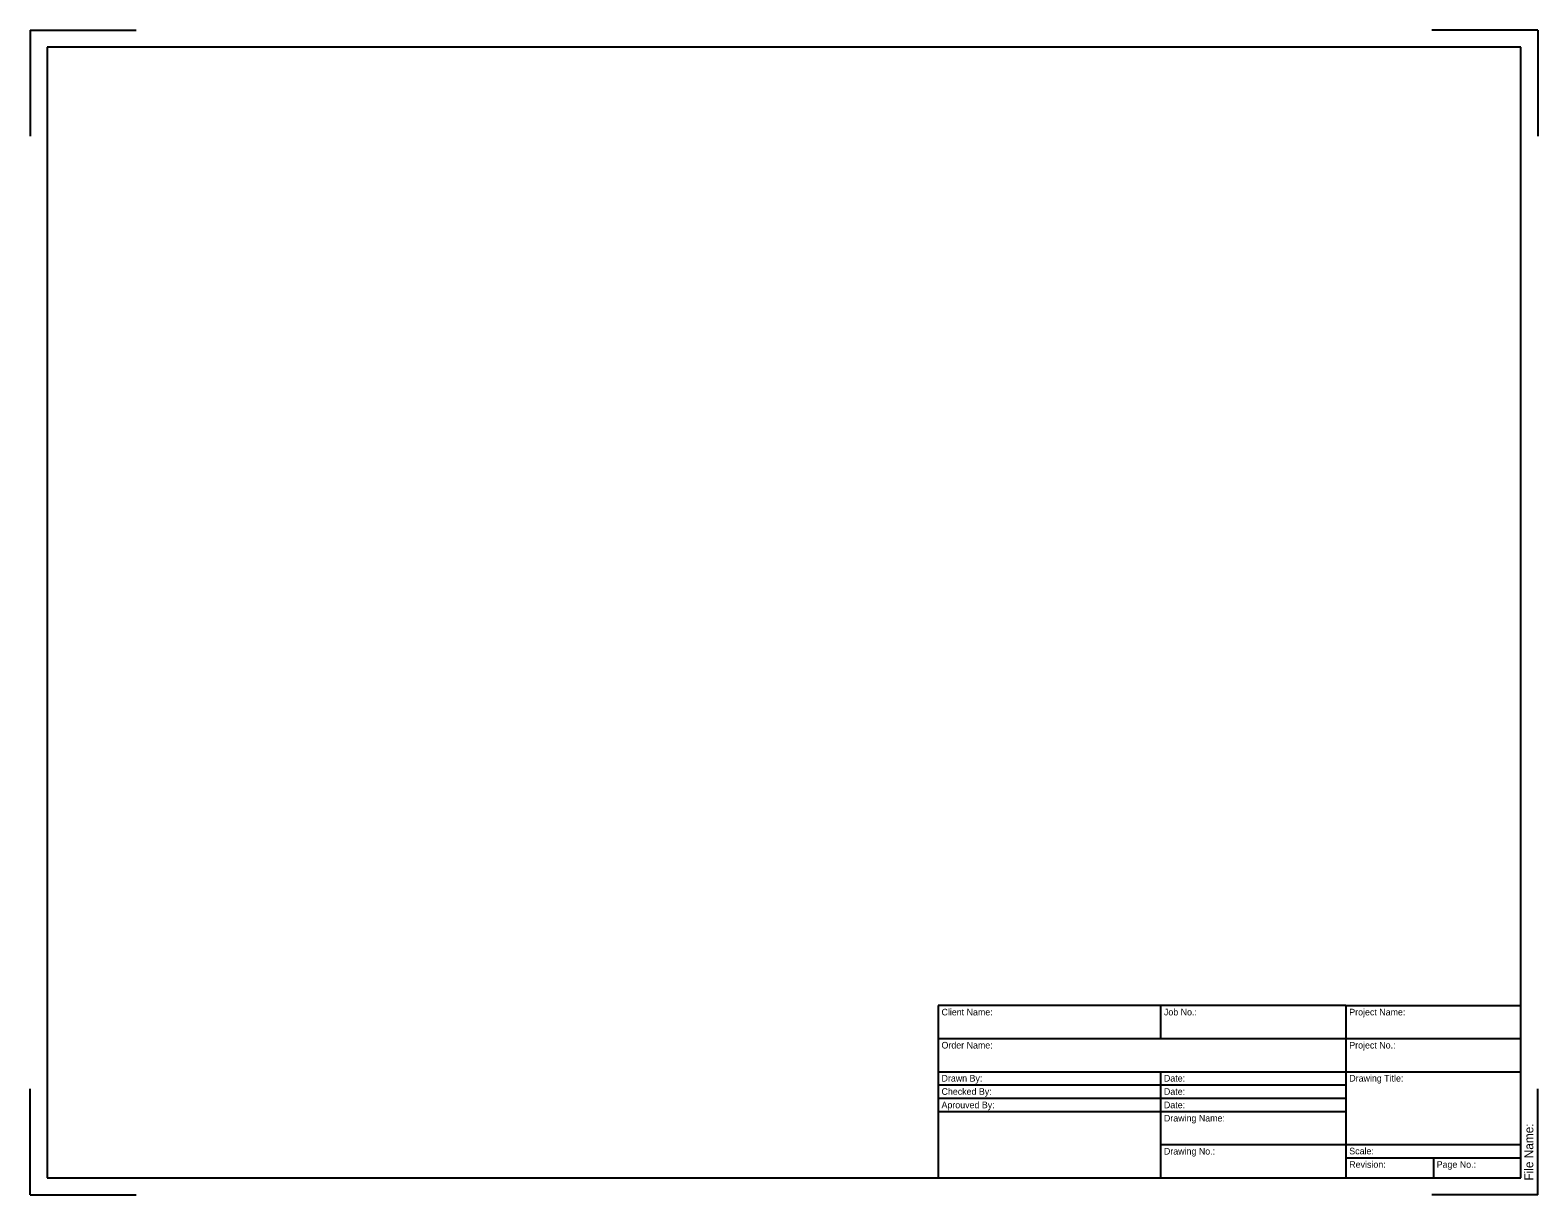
# Model space of a CAD drawing. Extents: x 0 to 44, y 0 to 34.
import ezdxf

# ---------------------------------------------------------------- set-up
doc = ezdxf.new("R2010")
doc.units = 0
doc.layers.add('STSF-BORDER', color=7, linetype='Continuous')

msp = doc.modelspace()

# ---------------------------------------------------------------- linework, layer by layer
at = {"layer": 'STSF-BORDER'}
for p, q in [((0, 34), (0, 30.909)), ((0, 34), (3.091, 34)), ((44, 34), (40.909, 34)), ((44, 34), (44, 30.909)), ((0.5, 33.5), (0.5, 0.5)), ((43.5, 33.5), (0.5, 33.5)), ((43.5, 0.5), (43.5, 33.5)), ((26.5, 5.528), (26.5, 0.5)), ((38.4, 5.528), (26.5, 5.528)), ((32.991, 5.528), (32.991, 4.562)), ((38.4, 5.528), (43.5, 5.528)), ((38.4, 5.528), (38.4, 0.5)), ((26.5, 4.562), (38.4, 4.562)), ((38.4, 4.562), (43.5, 4.562)), ((26.5, 3.596), (38.4, 3.596)), ((32.991, 3.596), (32.991, 0.5)), ((38.4, 3.596), (43.5, 3.596)), ((0, 0), (0, 3.091)), ((26.5, 3.21), (32.991, 3.21)), ((32.991, 3.21), (38.4, 3.21)), ((44, 0), (44, 3.091)), ((26.5, 2.824), (32.991, 2.824)), ((32.991, 2.824), (38.4, 2.824)), ((26.5, 2.432), (32.991, 2.432)), ((32.991, 2.432), (38.4, 2.432)), ((32.991, 1.466), (38.4, 1.466)), ((38.4, 1.471), (43.5, 1.471)), ((38.4, 1.085), (43.5, 1.085)), ((40.95, 1.085), (40.95, 0.5)), ((0.5, 0.5), (43.5, 0.5)), ((32.991, 0.5), (38.4, 0.5)), ((0, 0), (3.091, 0)), ((44, 0), (40.909, 0))]:
    msp.add_line(p, q, dxfattribs=at)

# ---------------------------------------------------------------- texts
for s, height, p in [('Client Name:', 0.19318, (26.597, 5.238)), ('Job No.:', 0.1932, (33.088, 5.238)), ('Project Name:', 0.19318, (38.497, 5.238)), ('Order Name:', 0.19318, (26.597, 4.272)), ('Project No.:', 0.19318, (38.497, 4.272)), ('Checked By:', 0.19318, (26.597, 2.92)), ('Drawn By:', 0.1932, (26.597, 3.307)), ('Date:', 0.1932, (33.088, 3.307)), ('Date:', 0.1932, (33.088, 2.92)), ('Drawing Title:', 0.19318, (38.497, 3.307)), ('Aprouved By:', 0.19318, (26.597, 2.528)), ('Date:', 0.1932, (33.088, 2.528)), ('Drawing Name:', 0.19318, (33.088, 2.142)), ('Drawing No.:', 0.19318, (33.088, 1.176)), ('Scale:', 0.1932, (38.497, 1.182)), ('Revision:', 0.1932, (38.497, 0.79)), ('Page No.:', 0.1932, (41.047, 0.79))]:
    msp.add_text(s, height=height, dxfattribs=at).set_placement(p)
msp.add_text('File Name:', height=0.2576, rotation=90, dxfattribs=at).set_placement((43.867, 0.418))

doc.saveas('drawing.dxf')
